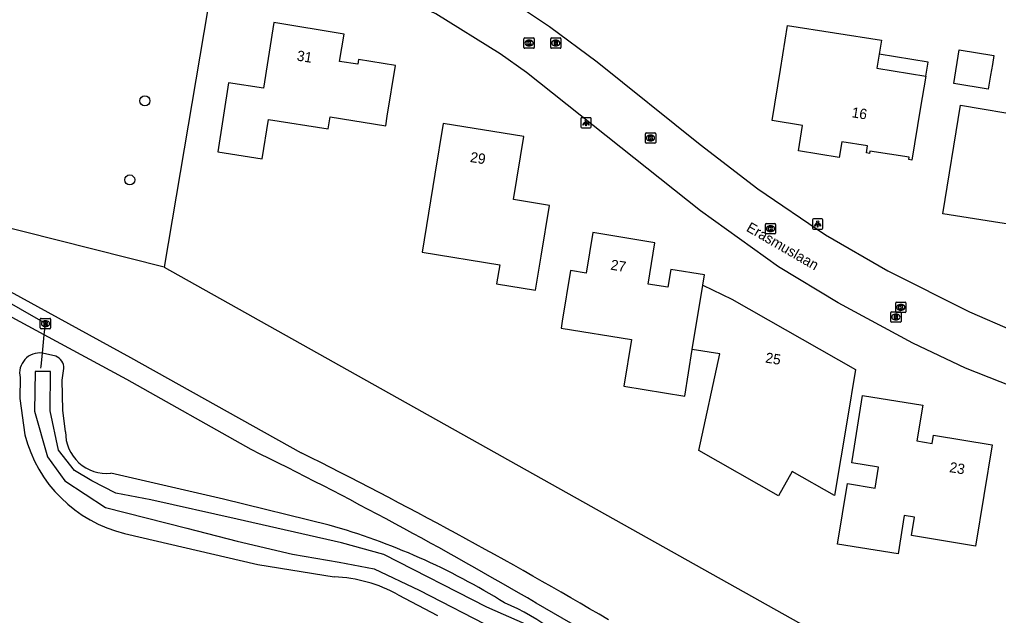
# Model space of a CAD drawing. Extents: x 163268 to 164360, y 381529 to 382285.
# Drawn here: x 163316.4 to 163411.7, y 381645.8 to 381703.8 of the extents above; entities that cross this region are included whole.
import ezdxf

# ---------------------------------------------------------------- set-up
doc = ezdxf.new("R2010")
doc.units = 0
for name, color, linetype in [('IMGEO_Boom', 7, 'Continuous'), ('IMGEO_Duiker', 7, 'Continuous'), ('IMGEO_Groenvoorziening', 7, 'Continuous'), ('IMGEO_Kolk', 7, 'Continuous'), ('IMGEO_Lichtpunt', 7, 'Continuous'), ('IMGEO_Loofbos', 7, 'Continuous'), ('IMGEO_Openbare_ruimte_label', 7, 'Continuous'), ('IMGEO_Pand', 7, 'Continuous'), ('IMGEO_Pand_nummerreeks', 7, 'Continuous'), ('IMGEO_Pand_overbouw', 7, 'Continuous'), ('IMGEO_Rijbaan_lokaal_open', 7, 'Continuous'), ('IMGEO_Rioolput', 7, 'Continuous'), ('IMGEO_Voetpad_halfverhard', 7, 'Continuous'), ('IMGEO_Waterloop', 7, 'Continuous')]:
    doc.layers.add(name, color=color, linetype=linetype)

msp = doc.modelspace()

# ---------------------------------------------------------------- linework, layer by layer
at = {"layer": 'IMGEO_Boom'}
for centre in [(163328.63, 381695.879), (163327.152, 381688.194)]:
    msp.add_circle(centre, 0.489, dxfattribs=at)
at = {"layer": 'IMGEO_Duiker'}
msp.add_lwpolyline([(163318.506, 381669.892), (163318.526, 381670.079), (163318.658, 381671.353), (163318.843, 381673.12), (163318.957, 381674.219), (163302.129, 381683.867), (163302.455, 381684.459), (163307.535, 381693.689), (163306.193, 381694.858), (163303.915, 381696.841), (163302.808, 381697.806), (163299.248, 381700.906)], dxfattribs=at)
at = {"layer": 'IMGEO_Groenvoorziening'}
msp.add_lwpolyline([(163330.491, 381679.719), (163413.518, 381633.213), (163417.487, 381666.326)], dxfattribs=at)
at = {"layer": 'IMGEO_Kolk'}
for p, q in [((163365.501, 381701.074), (163365.501, 381701.926)), ((163365.576, 381702), (163366.428, 381702)), ((163366.502, 381701.926), (163366.502, 381701.074)), ((163366.428, 381701), (163365.576, 381701)), ((163366.012, 381701.22), (163365.987, 381701.22)), ((163365.989, 381701.78), (163366.014, 381701.78)), ((163377.311, 381691.838), (163377.311, 381692.69)), ((163377.386, 381692.764), (163378.238, 381692.764)), ((163377.799, 381692.544), (163377.824, 381692.544)), ((163378.312, 381692.69), (163378.312, 381691.838)), ((163378.238, 381691.764), (163377.386, 381691.764)), ((163377.822, 381691.984), (163377.797, 381691.984)), ((163388.979, 381683.02), (163388.979, 381683.872)), ((163389.054, 381683.946), (163389.906, 381683.946)), ((163389.467, 381683.726), (163389.492, 381683.726)), ((163389.98, 381683.872), (163389.98, 381683.02)), ((163389.906, 381682.946), (163389.054, 381682.946)), ((163389.49, 381683.166), (163389.465, 381683.166)), ((163401.658, 381675.373), (163401.658, 381676.225)), ((163401.733, 381676.299), (163402.585, 381676.299)), ((163402.659, 381676.225), (163402.659, 381675.373)), ((163402.585, 381675.299), (163401.733, 381675.299)), ((163402.169, 381675.519), (163402.144, 381675.519)), ((163402.146, 381676.079), (163402.171, 381676.079))]:
    msp.add_line(p, q, dxfattribs=at)
for points in [[(163365.501, 381701.074), (163365.501, 381701.926)], [(163365.576, 381702), (163366.428, 381702)], [(163366.502, 381701.926), (163366.502, 381701.074)], [(163366.428, 381701), (163365.576, 381701)], [(163365.822, 381701.7), (163365.945, 381701.7), (163365.945, 381701.549), (163366.075, 381701.7), (163366.239, 381701.7), (163366.093, 381701.549), (163366.246, 381701.3), (163366.094, 381701.3), (163366.009, 381701.464), (163365.945, 381701.397), (163365.945, 381701.3), (163365.822, 381701.3), (163365.822, 381701.7)], [(163377.311, 381691.838), (163377.311, 381692.69)], [(163377.386, 381692.764), (163378.238, 381692.764)], [(163377.632, 381692.464), (163377.755, 381692.464), (163377.755, 381692.313), (163377.885, 381692.464), (163378.049, 381692.464), (163377.903, 381692.313), (163378.056, 381692.064), (163377.904, 381692.064), (163377.819, 381692.228), (163377.755, 381692.161), (163377.755, 381692.064), (163377.632, 381692.064), (163377.632, 381692.464)], [(163378.312, 381692.69), (163378.312, 381691.838)], [(163378.238, 381691.764), (163377.386, 381691.764)], [(163388.979, 381683.02), (163388.979, 381683.872)], [(163389.054, 381683.946), (163389.906, 381683.946)], [(163389.98, 381683.872), (163389.98, 381683.02)], [(163389.906, 381682.946), (163389.054, 381682.946)], [(163389.3, 381683.646), (163389.423, 381683.646), (163389.423, 381683.495), (163389.553, 381683.646), (163389.717, 381683.646), (163389.571, 381683.495), (163389.724, 381683.246), (163389.572, 381683.246), (163389.487, 381683.41), (163389.423, 381683.343), (163389.423, 381683.246), (163389.3, 381683.246), (163389.3, 381683.646)], [(163401.658, 381675.373), (163401.658, 381676.225)], [(163401.733, 381676.299), (163402.585, 381676.299)], [(163402.659, 381676.225), (163402.659, 381675.373)], [(163402.585, 381675.299), (163401.733, 381675.299)], [(163401.979, 381675.999), (163402.102, 381675.999), (163402.102, 381675.848), (163402.232, 381675.999), (163402.396, 381675.999), (163402.25, 381675.848), (163402.403, 381675.599), (163402.251, 381675.599), (163402.166, 381675.763), (163402.102, 381675.696), (163402.102, 381675.599), (163401.979, 381675.599), (163401.979, 381675.999)]]:
    msp.add_lwpolyline(points, dxfattribs=at)
for centre, start, end in [((163365.578, 381701.924), 91.55205, 178.44795), ((163365.578, 381701.924), 91.55205, 178.44795), ((163366.426, 381701.924), 1.55205, 88.44795), ((163366.426, 381701.924), 1.55205, 88.44795), ((163365.578, 381701.076), 181.55205, 268.44795), ((163365.578, 381701.076), 181.55205, 268.44795), ((163366.426, 381701.076), 271.55205, 358.44795), ((163366.426, 381701.076), 271.55205, 358.44795), ((163377.388, 381692.688), 91.55205, 178.44795), ((163377.388, 381692.688), 91.55205, 178.44795), ((163378.236, 381692.688), 1.55205, 88.44795), ((163378.236, 381692.688), 1.55205, 88.44795), ((163377.388, 381691.84), 181.55205, 268.44795), ((163377.388, 381691.84), 181.55205, 268.44795), ((163378.236, 381691.84), 271.55205, 358.44795), ((163378.236, 381691.84), 271.55205, 358.44795), ((163389.056, 381683.87), 91.55205, 178.44795), ((163389.056, 381683.87), 91.55205, 178.44795), ((163389.904, 381683.87), 1.55205, 88.44795), ((163389.904, 381683.87), 1.55205, 88.44795), ((163389.056, 381683.022), 181.55205, 268.44795), ((163389.056, 381683.022), 181.55205, 268.44795), ((163389.904, 381683.022), 271.55205, 358.44795), ((163389.904, 381683.022), 271.55205, 358.44795), ((163401.735, 381676.223), 91.55205, 178.44795), ((163401.735, 381676.223), 91.55205, 178.44795), ((163402.583, 381676.223), 1.55205, 88.44795), ((163402.583, 381676.223), 1.55205, 88.44795), ((163401.735, 381675.375), 181.55205, 268.44795), ((163401.735, 381675.375), 181.55205, 268.44795), ((163402.583, 381675.375), 271.55205, 358.44795), ((163402.583, 381675.375), 271.55205, 358.44795)]:
    msp.add_arc(centre, 0.0765, start, end, dxfattribs=at)
for centre, major_axis, ratio, start_param, end_param in [((163365.988, 381701.5), (-0.387, 0.002), 0.722429, 4.712389, 7.853982), ((163366.013, 381701.5), (-0.39, 0.002), 0.717154, 1.570796, 4.712389), ((163377.798, 381692.264), (-0.387, 0.002), 0.722429, 4.712389, 7.853982), ((163377.823, 381692.264), (-0.39, 0.002), 0.717154, 1.570796, 4.712389), ((163389.466, 381683.446), (-0.387, 0.002), 0.722429, 4.712389, 7.853982), ((163389.491, 381683.446), (-0.39, 0.002), 0.717154, 1.570796, 4.712389), ((163402.145, 381675.799), (-0.387, 0.002), 0.722429, 4.712389, 7.853982), ((163402.17, 381675.799), (-0.39, 0.002), 0.717154, 1.570796, 4.712389)]:
    msp.add_ellipse(centre, major_axis=major_axis, ratio=ratio, start_param=start_param, end_param=end_param, dxfattribs=at)
at = {"layer": 'IMGEO_Lichtpunt'}
for p, q in [((163371.944, 381694.245), (163371.136, 381694.245)), ((163371.944, 381694.245), (163371.136, 381694.245)), ((163371.042, 381694.15), (163371.042, 381693.343)), ((163371.042, 381694.15), (163371.042, 381693.343)), ((163371.136, 381693.249), (163371.944, 381693.249)), ((163371.136, 381693.249), (163371.944, 381693.249)), ((163372.038, 381693.343), (163372.038, 381694.15)), ((163372.038, 381693.343), (163372.038, 381694.15)), ((163393.575, 381684.311), (163393.575, 381683.504)), ((163393.575, 381684.311), (163393.575, 381683.504)), ((163394.477, 381684.406), (163393.669, 381684.406)), ((163394.477, 381684.406), (163393.669, 381684.406)), ((163394.571, 381683.504), (163394.571, 381684.311)), ((163394.571, 381683.504), (163394.571, 381684.311)), ((163393.669, 381683.41), (163394.477, 381683.41)), ((163393.669, 381683.41), (163394.477, 381683.41))]:
    msp.add_line(p, q, dxfattribs=at)
for points in [[(163371.416, 381693.814), (163371.455, 381693.786), (163371.267, 381693.524), (163371.229, 381693.551), (163371.416, 381693.814)], [(163371.518, 381693.766), (163371.565, 381693.766), (163371.565, 381693.444), (163371.518, 381693.444), (163371.518, 381693.766)], [(163371.628, 381693.786), (163371.666, 381693.813), (163371.853, 381693.551), (163371.814, 381693.523), (163371.628, 381693.786)], [(163393.949, 381683.975), (163393.988, 381683.947), (163393.8, 381683.685), (163393.762, 381683.712), (163393.949, 381683.975)], [(163394.051, 381683.927), (163394.098, 381683.927), (163394.098, 381683.605), (163394.051, 381683.605), (163394.051, 381683.927)], [(163394.161, 381683.947), (163394.199, 381683.974), (163394.386, 381683.712), (163394.347, 381683.684), (163394.161, 381683.947)]]:
    msp.add_lwpolyline(points, dxfattribs=at)
for centre in [(163371.541, 381693.948), (163394.074, 381684.109)]:
    msp.add_circle(centre, 0.0994, dxfattribs=at)
for centre, start, end in [((163371.136, 381694.15), 90, 180), ((163371.136, 381694.15), 90, 180), ((163371.944, 381694.15), 0, 90), ((163371.944, 381694.15), 0, 90), ((163371.136, 381693.343), 180, 270), ((163371.136, 381693.343), 180, 270), ((163371.944, 381693.343), 270, 0), ((163371.944, 381693.343), 270, 360), ((163393.669, 381684.311), 90, 180), ((163393.669, 381684.311), 90, 180), ((163394.477, 381684.311), 0, 90), ((163394.477, 381684.311), 0, 90), ((163393.669, 381683.504), 180, 270), ((163393.669, 381683.504), 180, 270), ((163394.477, 381683.504), 270, 0), ((163394.477, 381683.504), 270, 360)]:
    msp.add_arc(centre, 0.0946, start, end, dxfattribs=at)
at = {"layer": 'IMGEO_Loofbos'}
for points in [[(163336.032, 381712.46), (163335.527, 381709.472), (163330.491, 381679.719)], [(163330.491, 381679.719), (163330.491, 381679.717), (163309.778, 381684.922), (163308.444, 381681.187)], [(163319.959, 381671.043), (163318.658, 381671.353)], [(163320.909, 381663.69), (163320.641, 381665.802), (163320.568, 381668.717), (163320.734, 381669.843)], [(163316.489, 381668.969), (163316.452, 381666.923), (163316.953, 381663.396)], [(163346.543, 381654.627), (163336.263, 381657.151), (163325.312, 381659.673)], [(163326.647, 381653.81), (163339.603, 381650.774), (163347.051, 381649.58)], [(163353.252, 381647.836), (163357.098, 381645.834)]]:
    msp.add_lwpolyline(points, dxfattribs=at)
for centre, radius, start, end in [((163318.41, 381669.4), 1.969, 82.76654, 192.64064), ((163319.544, 381669.925), 1.192, 356.05954, 69.6519), ((163329.764, 381666.657), 13.22, 194.28131, 256.36059), ((163324.878, 381663.619), 3.97, 178.97625, 276.27332), ((163328.351, 381590.591), 66.57, 58.009, 74.14077), ((163346.539, 381635.864), 13.726, 60.72024, 87.86302), ((163356.413, 381629.205), 19.246, 34.56865, 68.01154)]:
    msp.add_arc(centre, radius, start, end, dxfattribs=at)
at = {"layer": 'IMGEO_Pand'}
for points in [[(163352.208, 381694.393), (163353.01, 381699.327), (163349.403, 381699.914), (163349.325, 381699.437), (163347.565, 381699.723), (163347.997, 381702.38), (163341.166, 381703.491), (163340.157, 381697.114), (163336.775, 381697.648), (163335.71, 381690.914), (163340.034, 381690.231), (163340.641, 381694.078), (163346.452, 381693.159), (163346.644, 381694.336), (163352.055, 381693.456), (163352.208, 381694.393)], [(163404.052, 381695.062), (163403.239, 381690.128), (163402.933, 381690.177), (163402.968, 381690.395), (163399.155, 381690.993), (163399.12, 381690.775), (163398.804, 381690.824), (163398.91, 381691.496), (163396.41, 381691.888), (163396.151, 381690.375), (163392.195, 381691.019), (163392.599, 381693.497), (163389.642, 381693.981), (163390.449, 381698.916), (163391.151, 381703.208), (163400.265, 381701.788), (163400.042, 381700.436), (163399.814, 381699.055), (163404.58, 381698.27), (163404.052, 381695.062)], [(163411.065, 381699.426), (163410.895, 381698.389), (163410.669, 381697.019), (163407.302, 381697.574), (163407.843, 381700.854), (163411.209, 381700.299), (163411.065, 381699.426)], [(163414.488, 381694.376), (163415.052, 381697.731), (163422.979, 381696.425), (163421.641, 381688.408), (163421.172, 381688.485), (163419.707, 381679.675), (163412.852, 381680.79), (163413.315, 381683.775), (163411.785, 381684.019), (163406.237, 381684.903), (163407.975, 381695.449), (163414.488, 381694.376)], [(163367.167, 381680.776), (163367.969, 381685.71), (163364.482, 381686.277), (163365.48, 381692.412), (163357.627, 381693.689), (163356.825, 381688.754), (163355.592, 381681.173), (163363.141, 381679.945), (163362.839, 381678.094), (163366.63, 381677.477), (163367.167, 381680.776)], [(163382.897, 381677.96), (163383.058, 381678.957), (163379.776, 381679.491), (163379.493, 381677.751), (163377.585, 381678.061), (163378.24, 381682.086), (163372.194, 381683.069), (163371.552, 381679.127), (163370.027, 381679.375), (163369.225, 381674.44), (163369.117, 381673.777), (163375.959, 381672.664), (163375.217, 381668.124), (163381.133, 381667.162), (163381.875, 381671.701)], [(163381.875, 381671.701), (163382.897, 381677.96)], [(163382.897, 381677.96), (163385.718, 381676.59), (163397.763, 381669.745), (163396.932, 381664.815), (163395.696, 381657.489), (163391.587, 381659.824), (163390.253, 381657.476), (163382.512, 381661.875), (163384.558, 381671.265), (163381.875, 381671.701)], [(163398.443, 381667.228), (163404.288, 381666.278), (163403.724, 381662.807), (163405.195, 381662.568), (163405.322, 381663.35), (163411.028, 381662.422), (163410.226, 381657.488), (163409.428, 381652.586), (163403.19, 381653.601), (163403.479, 381655.377), (163402.49, 381655.538), (163401.884, 381651.81), (163396, 381652.767), (163396.959, 381658.661), (163399.667, 381658.22), (163399.997, 381660.25), (163397.377, 381660.676), (163397.64, 381662.293), (163398.443, 381667.228)]]:
    msp.add_lwpolyline(points, dxfattribs=at)
at = {"layer": 'IMGEO_Pand_overbouw'}
msp.add_lwpolyline([(163404.58, 381698.27), (163404.808, 381699.651), (163400.042, 381700.436), (163399.814, 381699.055)], close=True, dxfattribs=at)
at = {"layer": 'IMGEO_Rijbaan_lokaal_open'}
for points in [[(163336.795, 381717.345), (163351.762, 381712.267), (163355.051, 381710.889), (163362.159, 381707.029), (163367.988, 381703.121), (163372.635, 381699.671), (163382.632, 381691.621), (163388.244, 381687.318), (163394.839, 381682.863), (163400.907, 381679.343), (163408.849, 381675.346), (163417.211, 381671.729), (163424.267, 381669.269)], [(163417.487, 381666.326), (163408.435, 381669.883), (163403.317, 381672.32), (163396.047, 381676.226), (163390.269, 381679.724), (163382.665, 381685.191), (163365.756, 381698.629), (163363.185, 381700.457), (163356.936, 381704.332), (163350.46, 381707.4), (163339.976, 381711.167), (163336.032, 381712.46)]]:
    msp.add_lwpolyline(points, dxfattribs=at)
at = {"layer": 'IMGEO_Rioolput'}
for p, q in [((163368.098, 381701.073), (163368.098, 381701.925)), ((163368.173, 381701.999), (163369.025, 381701.999)), ((163369.099, 381701.925), (163369.099, 381701.073)), ((163369.025, 381700.999), (163368.173, 381700.999)), ((163368.609, 381701.219), (163368.584, 381701.219)), ((163368.586, 381701.779), (163368.611, 381701.779)), ((163401.176, 381674.432), (163401.176, 381675.284)), ((163401.251, 381675.358), (163402.103, 381675.358)), ((163401.664, 381675.138), (163401.689, 381675.138)), ((163402.177, 381675.284), (163402.177, 381674.432)), ((163318.456, 381673.793), (163318.456, 381674.645)), ((163318.531, 381674.719), (163319.383, 381674.719)), ((163318.944, 381674.499), (163318.969, 381674.499)), ((163319.457, 381674.645), (163319.457, 381673.793)), ((163402.103, 381674.358), (163401.251, 381674.358)), ((163401.687, 381674.578), (163401.662, 381674.578)), ((163319.383, 381673.719), (163318.531, 381673.719)), ((163318.967, 381673.939), (163318.942, 381673.939))]:
    msp.add_line(p, q, dxfattribs=at)
for points in [[(163368.098, 381701.073), (163368.098, 381701.925)], [(163368.173, 381701.999), (163369.025, 381701.999)], [(163369.099, 381701.925), (163369.099, 381701.073)], [(163369.025, 381700.999), (163368.173, 381700.999)], [(163368.687, 381701.697), (163368.435, 381701.699), (163368.435, 381701.299)], [(163368.435, 381701.299), (163368.559, 381701.299), (163368.559, 381701.461), (163368.57, 381701.461)], [(163368.613, 381701.618), (163368.559, 381701.618), (163368.559, 381701.537)], [(163368.559, 381701.537), (163368.611, 381701.537)], [(163368.617, 381701.432), (163368.688, 381701.299), (163368.828, 381701.299), (163368.763, 381701.425)], [(163401.176, 381674.432), (163401.176, 381675.284)], [(163401.251, 381675.358), (163402.103, 381675.358)], [(163402.177, 381675.284), (163402.177, 381674.432)], [(163318.456, 381673.793), (163318.456, 381674.645)], [(163318.531, 381674.719), (163319.383, 381674.719)], [(163319.045, 381674.417), (163318.793, 381674.419), (163318.793, 381674.019)], [(163318.793, 381674.019), (163318.917, 381674.019), (163318.917, 381674.181), (163318.928, 381674.181)], [(163318.971, 381674.338), (163318.917, 381674.338), (163318.917, 381674.257)], [(163318.917, 381674.257), (163318.969, 381674.257)], [(163319.457, 381674.645), (163319.457, 381673.793)], [(163402.103, 381674.358), (163401.251, 381674.358)], [(163401.765, 381675.056), (163401.513, 381675.058), (163401.513, 381674.658)], [(163401.513, 381674.658), (163401.637, 381674.658), (163401.637, 381674.82), (163401.648, 381674.82)], [(163401.691, 381674.977), (163401.637, 381674.977), (163401.637, 381674.896)], [(163401.637, 381674.896), (163401.689, 381674.896)], [(163401.695, 381674.791), (163401.766, 381674.658), (163401.906, 381674.658), (163401.841, 381674.784)], [(163319.383, 381673.719), (163318.531, 381673.719)], [(163318.975, 381674.152), (163319.046, 381674.019), (163319.186, 381674.019), (163319.121, 381674.145)]]:
    msp.add_lwpolyline(points, dxfattribs=at)
for centre, radius, start, end in [((163368.175, 381701.923), 0.0765, 91.55205, 178.44795), ((163368.175, 381701.923), 0.0765, 91.55205, 178.44795), ((163369.023, 381701.923), 0.0765, 1.55205, 88.44795), ((163369.023, 381701.923), 0.0765, 1.55205, 88.44795), ((163368.175, 381701.075), 0.0765, 181.55205, 268.44795), ((163368.175, 381701.075), 0.0765, 181.55205, 268.44795), ((163368.569, 381701.408), 0.0533, 26.02933, 88.69889), ((163368.595, 381701.726), 0.19, 274.7715, 282.96867), ((163368.619, 381701.522), 0.0964, 77.00612, 93.18647), ((163368.633, 381701.579), 0.0378, 276.66336, 79.67722), ((163368.686, 381701.587), 0.109, 350.36119, 89.41601), ((163368.684, 381701.587), 0.112, 277.58423, 350.98172), ((163368.668, 381701.372), 0.108, 29.51342, 73.79051), ((163369.023, 381701.075), 0.0765, 271.55205, 358.44795), ((163369.023, 381701.075), 0.0765, 271.55205, 358.44795), ((163401.253, 381675.282), 0.0765, 91.55205, 178.44795), ((163401.253, 381675.282), 0.0765, 91.55205, 178.44795), ((163402.101, 381675.282), 0.0765, 1.55205, 88.44795), ((163402.101, 381675.282), 0.0765, 1.55205, 88.44795), ((163318.533, 381674.643), 0.0765, 91.55205, 178.44795), ((163318.533, 381674.643), 0.0765, 91.55205, 178.44795), ((163318.927, 381674.128), 0.0533, 26.02933, 88.69889), ((163318.953, 381674.446), 0.19, 274.7715, 282.96867), ((163318.977, 381674.242), 0.0964, 77.00612, 93.18647), ((163318.991, 381674.299), 0.0378, 276.66336, 79.67722), ((163319.044, 381674.307), 0.109, 350.36119, 89.41601), ((163319.042, 381674.307), 0.112, 277.58423, 350.98172), ((163319.026, 381674.092), 0.108, 29.51342, 73.79051), ((163319.381, 381674.643), 0.0765, 1.55205, 88.44795), ((163319.381, 381674.643), 0.0765, 1.55205, 88.44795), ((163401.253, 381674.434), 0.0765, 181.55205, 268.44795), ((163401.253, 381674.434), 0.0765, 181.55205, 268.44795), ((163401.647, 381674.767), 0.0533, 26.02933, 88.69889), ((163401.673, 381675.085), 0.19, 274.7715, 282.96867), ((163401.697, 381674.881), 0.0964, 77.00612, 93.18647), ((163401.711, 381674.938), 0.0378, 276.66336, 79.67722), ((163401.764, 381674.946), 0.109, 350.36119, 89.41601), ((163401.762, 381674.946), 0.112, 277.58423, 350.98172), ((163401.746, 381674.731), 0.108, 29.51342, 73.79051), ((163402.101, 381674.434), 0.0765, 271.55205, 358.44795), ((163402.101, 381674.434), 0.0765, 271.55205, 358.44795), ((163318.533, 381673.795), 0.0765, 181.55205, 268.44795), ((163318.533, 381673.795), 0.0765, 181.55205, 268.44795), ((163319.381, 381673.795), 0.0765, 271.55205, 358.44795), ((163319.381, 381673.795), 0.0765, 271.55205, 358.44795)]:
    msp.add_arc(centre, radius, start, end, dxfattribs=at)
for centre, major_axis, ratio, start_param, end_param in [((163368.585, 381701.499), (-0.387, 0.002), 0.722429, 4.712389, 7.853982), ((163368.61, 381701.499), (-0.39, 0.002), 0.717154, 1.570796, 4.712389), ((163401.663, 381674.858), (-0.387, 0.002), 0.722429, 4.712389, 7.853982), ((163401.688, 381674.858), (-0.39, 0.002), 0.717154, 1.570796, 4.712389), ((163318.943, 381674.219), (-0.387, 0.002), 0.722429, 4.712389, 7.853982), ((163318.968, 381674.219), (-0.39, 0.002), 0.717154, 1.570796, 4.712389)]:
    msp.add_ellipse(centre, major_axis=major_axis, ratio=ratio, start_param=start_param, end_param=end_param, dxfattribs=at)
at = {"layer": 'IMGEO_Voetpad_halfverhard'}
for points in [[(163308.444, 381681.187), (163327.231, 381670.924), (163343.841, 381661.648)], [(163338.965, 381661.969), (163326.867, 381668.777), (163318.843, 381673.12), (163307.547, 381679.234)], [(163438.809, 381600.427), (163438.464, 381600.706), (163429.218, 381608.183), (163413.891, 381619.182), (163386.457, 381635.598), (163366.682, 381647.039)]]:
    msp.add_lwpolyline(points, dxfattribs=at)
for centre, radius, start, end in [((163145.282, 381269.212), 437.917, 59.63052, 63.75046), ((163123.26, 381220.055), 493.62, 59.50979, 63.45729)]:
    msp.add_arc(centre, radius, start, end, dxfattribs=at)
at = {"layer": 'IMGEO_Waterloop'}
msp.add_lwpolyline([(163365.656, 381644.981), (163361.876, 381646.637), (163351.855, 381651.775), (163347.736, 381652.879), (163337.588, 381655.193), (163329.201, 381657.083), (163325.804, 381657.72), (163323.474, 381658.909), (163321.781, 381659.939), (163320.215, 381661.908), (163319.408, 381665.729), (163319.451, 381669.551), (163317.965, 381669.551), (163317.88, 381665.687), (163319.154, 381661.271), (163320.852, 381658.935), (163324.801, 381656.345), (163332.699, 381654.307), (163337.609, 381653.049), (163342.975, 381651.802), (163347.519, 381651.016), (163350.916, 381650.379), (163355.311, 381648.298), (163362.72, 381644.477)], dxfattribs=at)

# ---------------------------------------------------------------- texts
at = {"layer": 'IMGEO_Openbare_ruimte_label'}
msp.add_text('Erasmuslaan', height=1, rotation=329.94968, dxfattribs=at).set_placement((163387.044, 381683.274))
at = {"layer": 'IMGEO_Pand_nummerreeks'}
for s, rotation, p in [('31', 350.76225, (163343.351, 381699.812)), ('16', 351.09051, (163397.323, 381694.295)), ('29', 350.76381, (163360.211, 381689.946)), ('27', 350.76527, (163373.875, 381679.473)), ('25', 350.72381, (163388.929, 381670.438)), ('23', 350.76253, (163406.832, 381659.782))]:
    msp.add_text(s, height=1, rotation=rotation, dxfattribs=at).set_placement(p)

doc.saveas('drawing.dxf')
